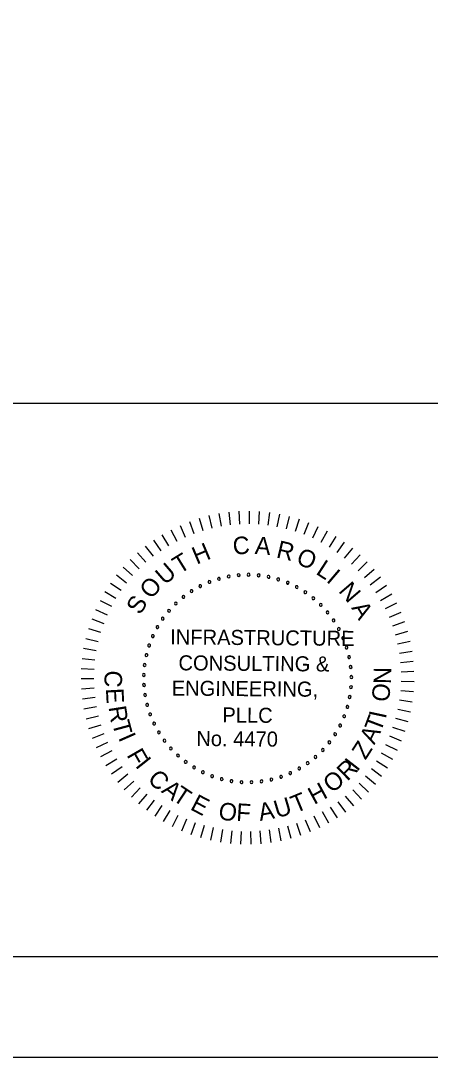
# Model space of a CAD drawing. Extents: x -125.5 to -89.4, y -5.1 to 16.9.
# Drawn here: x -100.33 to -98.29, y -5.07 to 0.08 of the extents above; entities that cross this region are included whole.
import ezdxf

# ---------------------------------------------------------------- set-up
doc = ezdxf.new("R2010")
doc.units = 0
for name, color, linetype in [('BR_BORDER LINES', 7, 'Continuous'), ('BR_TEXT', 7, 'Continuous'), ('Level 31', 7, 'Continuous')]:
    doc.layers.add(name, color=color, linetype=linetype)

msp = doc.modelspace()

# ---------------------------------------------------------------- linework, layer by layer
at = {"layer": 'BR_BORDER LINES'}
for p, q in [((-102.8989, -1.8161), (-97.5337, -1.8161)), ((-123.6994, -4.5662), (-90.0334, -4.5662))]:
    msp.add_line(p, q, dxfattribs=at)
at = {"layer": 'BR_TEXT'}
for p, q in [((-99.343, -2.3651), (-99.332, -2.4278)), ((-99.2931, -2.3579), (-99.2858, -2.4212)), ((-99.2427, -2.3538), (-99.2394, -2.4174)), ((-99.1923, -2.3527), (-99.1928, -2.4164)), ((-99.1418, -2.3548), (-99.1462, -2.4183)), ((-99.0916, -2.3599), (-99.0999, -2.423)), ((-99.0418, -2.368), (-99.0539, -2.4305)), ((-99.489, -2.4048), (-99.4667, -2.4644)), ((-99.4412, -2.3886), (-99.4226, -2.4495)), ((-99.3925, -2.3754), (-99.3776, -2.4373)), ((-98.9925, -2.3792), (-99.0084, -2.4408)), ((-98.9441, -2.3933), (-98.9637, -2.4539)), ((-98.8966, -2.4104), (-98.9199, -2.4696)), ((-99.6253, -2.4703), (-99.5926, -2.5249)), ((-99.5813, -2.4457), (-99.5519, -2.5022)), ((-99.5358, -2.4238), (-99.5099, -2.482)), ((-98.8502, -2.4303), (-98.877, -2.488)), ((-98.8051, -2.453), (-98.8354, -2.509)), ((-99.6678, -2.4975), (-99.6318, -2.55)), ((-98.7615, -2.4785), (-98.7952, -2.5325)), ((-98.7195, -2.5065), (-98.7564, -2.5584)), ((-99.7475, -2.5595), (-99.7053, -2.6072)), ((-99.7086, -2.5273), (-99.6694, -2.5775)), ((-98.6793, -2.5371), (-98.7193, -2.5866)), ((-98.6411, -2.57), (-98.684, -2.617)), ((-99.7843, -2.5941), (-99.7393, -2.6391)), ((-98.6049, -2.6052), (-98.6506, -2.6495)), ((-99.8513, -2.6695), (-99.8012, -2.7087)), ((-99.819, -2.6308), (-99.7713, -2.673)), ((-98.571, -2.6426), (-98.6193, -2.684)), ((-99.8813, -2.7102), (-99.8288, -2.7463)), ((-98.5393, -2.6819), (-98.5901, -2.7204)), ((-98.5102, -2.7232), (-98.5632, -2.7584)), ((-99.9087, -2.7526), (-99.8541, -2.7854)), ((-98.4836, -2.7661), (-98.5387, -2.798)), ((-99.9334, -2.7966), (-99.877, -2.826)), ((-98.4597, -2.8105), (-98.5166, -2.839)), ((-99.9555, -2.842), (-99.8973, -2.8679)), ((-98.4385, -2.8564), (-98.497, -2.8814)), ((-99.9747, -2.8886), (-99.9151, -2.911)), ((-98.4201, -2.9034), (-98.4801, -2.9248)), ((-100.0044, -2.9851), (-99.9426, -3)), ((-99.991, -2.9364), (-99.9302, -2.9551)), ((-98.4047, -2.9515), (-98.4659, -2.9691)), ((-100.0149, -3.0345), (-99.9522, -3.0456)), ((-98.3922, -3.0004), (-98.4544, -3.0143)), ((-100.0222, -3.0844), (-99.959, -3.0917)), ((-98.3828, -3.05), (-98.4456, -3.0601)), ((-100.0266, -3.1347), (-99.963, -3.1382)), ((-98.3763, -3.1), (-98.4397, -3.1063)), ((-100.0278, -3.1852), (-99.9641, -3.1847)), ((-98.373, -3.1504), (-98.4366, -3.1528)), ((-100.026, -3.2356), (-99.9625, -3.2313)), ((-98.3727, -3.2009), (-98.4363, -3.1994)), ((-100.0211, -3.2859), (-99.9579, -3.2777)), ((-98.3813, -3.3014), (-98.4443, -3.2922)), ((-98.3755, -3.2513), (-98.4389, -3.2459)), ((-100.0131, -3.3357), (-99.9506, -3.3237)), ((-98.3902, -3.3511), (-98.4525, -3.3381)), ((-100.0021, -3.385), (-99.9405, -3.3692)), ((-98.4021, -3.4002), (-98.4635, -3.3834)), ((-99.9882, -3.4335), (-99.9276, -3.414)), ((-98.417, -3.4484), (-98.4773, -3.4279)), ((-99.9713, -3.4811), (-99.912, -3.4579)), ((-99.9515, -3.5276), (-99.8937, -3.5008)), ((-98.4348, -3.4957), (-98.4937, -3.4715)), ((-99.9289, -3.5727), (-99.8729, -3.5425)), ((-98.4554, -3.5417), (-98.5128, -3.514)), ((-99.9037, -3.6164), (-99.8496, -3.5828)), ((-98.5049, -3.6297), (-98.5585, -3.5952)), ((-98.4789, -3.5865), (-98.5344, -3.5553)), ((-99.8758, -3.6585), (-99.8239, -3.6217)), ((-98.5336, -3.6712), (-98.5849, -3.6335)), ((-99.8454, -3.6988), (-99.7958, -3.6589)), ((-99.8126, -3.7372), (-99.7655, -3.6943)), ((-98.5983, -3.7487), (-98.6447, -3.705)), ((-98.5648, -3.7109), (-98.6137, -3.6702)), ((-99.7775, -3.7735), (-99.7331, -3.7278)), ((-98.6341, -3.7843), (-98.6777, -3.7379)), ((-99.7403, -3.8076), (-99.6988, -3.7593)), ((-99.701, -3.8393), (-99.6626, -3.7886)), ((-98.7118, -3.8487), (-98.7494, -3.7974)), ((-98.6719, -3.8177), (-98.7126, -3.7687)), ((-99.6599, -3.8687), (-99.6246, -3.8157)), ((-99.6171, -3.8954), (-99.5851, -3.8404)), ((-98.7967, -3.9032), (-98.8278, -3.8476)), ((-98.7534, -3.8772), (-98.7879, -3.8237)), ((-99.5728, -3.9195), (-99.5442, -3.8626)), ((-99.527, -3.9408), (-99.5019, -3.8823)), ((-99.48, -3.9594), (-99.4586, -3.8994)), ((-98.935, -3.9645), (-98.9555, -3.9042)), ((-98.8877, -3.9469), (-98.9118, -3.888)), ((-98.8416, -3.9264), (-98.8692, -3.8691)), ((-99.432, -3.975), (-99.4143, -3.9138)), ((-99.3832, -3.9876), (-99.3692, -3.9255)), ((-99.3336, -3.9973), (-99.3234, -3.9344)), ((-99.2836, -4.0039), (-99.2772, -3.9406)), ((-99.2332, -4.0075), (-99.2307, -3.9438)), ((-99.1827, -4.0079), (-99.1841, -3.9443)), ((-99.1323, -4.0053), (-99.1376, -3.9419)), ((-99.0821, -3.9997), (-99.0913, -3.9367)), ((-99.0324, -3.991), (-99.0454, -3.9286)), ((-98.9833, -3.9792), (-99.0001, -3.9178))]:
    msp.add_line(p, q, dxfattribs=at)
for centre, start, end in [((-99.2939, -2.6775), 10.6038, 190.6038), ((-99.2939, -2.6775), 190.6038, 10.6038), ((-99.2445, -2.6708), 5.0653, 185.0653), ((-99.2445, -2.6708), 185.0653, 5.0653), ((-99.1947, -2.6689), 359.5268, 179.5268), ((-99.1947, -2.6689), 179.5268, 359.5268), ((-99.145, -2.6718), 173.9884, 353.9884), ((-99.145, -2.6718), 353.9884, 173.9884), ((-99.0957, -2.6795), 348.4499, 168.4499), ((-99.435, -2.7255), 27.2191, 207.2191), ((-99.435, -2.7255), 207.2191, 27.2191), ((-99.3895, -2.705), 21.6807, 201.6807), ((-99.3895, -2.705), 201.6807, 21.6807), ((-99.3424, -2.6889), 16.1422, 196.1422), ((-99.3424, -2.6889), 196.1422, 16.1422), ((-99.0957, -2.6795), 168.4499, 348.4499), ((-99.0475, -2.6919), 162.9114, 342.9114), ((-99.0475, -2.6919), 342.9114, 162.9114), ((-99.0006, -2.709), 157.373, 337.373), ((-99.0006, -2.709), 337.373, 157.373), ((-98.9557, -2.7304), 151.8345, 331.8345), ((-98.9557, -2.7304), 331.8345, 151.8345), ((-99.5188, -2.7792), 38.2961, 218.2961), ((-99.5188, -2.7792), 218.2961, 38.2961), ((-99.4782, -2.7503), 32.7576, 212.7576), ((-99.4782, -2.7503), 212.7576, 32.7576), ((-98.913, -2.7561), 146.2961, 326.2961), ((-98.913, -2.7561), 326.2961, 146.2961), ((-98.873, -2.7858), 320.7576, 140.7576), ((-99.5564, -2.8119), 43.8345, 223.8345), ((-99.5564, -2.8119), 223.8345, 43.8345), ((-98.873, -2.7858), 140.7576, 320.7576), ((-98.836, -2.8192), 135.2191, 315.2191), ((-98.836, -2.8192), 315.2191, 135.2191), ((-99.6214, -2.8873), 54.9114, 234.9114), ((-99.6214, -2.8873), 234.9114, 54.9114), ((-99.5907, -2.848), 49.373, 229.373), ((-99.5907, -2.848), 229.373, 49.373), ((-98.8024, -2.8561), 129.6807, 309.6807), ((-98.8024, -2.8561), 309.6807, 129.6807), ((-99.6481, -2.9293), 60.4499, 240.4499), ((-99.6481, -2.9293), 240.4499, 60.4499), ((-98.7726, -2.896), 124.1422, 304.1422), ((-98.7726, -2.896), 304.1422, 124.1422), ((-98.7467, -2.9386), 118.6038, 298.6038), ((-98.7467, -2.9386), 298.6038, 118.6038), ((-99.6706, -2.9738), 65.9884, 245.9884), ((-99.6706, -2.9738), 245.9884, 65.9884), ((-98.7251, -2.9835), 113.0653, 293.0653), ((-98.7251, -2.9835), 293.0653, 113.0653), ((-99.6888, -3.0202), 71.5268, 251.5268), ((-99.6888, -3.0202), 251.5268, 71.5268), ((-98.7079, -3.0302), 107.5268, 287.5268), ((-98.7079, -3.0302), 287.5268, 107.5268), ((-99.7024, -3.0681), 77.0653, 257.0653), ((-99.7024, -3.0681), 257.0653, 77.0653), ((-98.6953, -3.0785), 101.9884, 281.9884), ((-98.6953, -3.0785), 281.9884, 101.9884), ((-99.7113, -3.1172), 82.6038, 262.6038), ((-99.7113, -3.1172), 262.6038, 82.6038), ((-98.6874, -3.1277), 96.4499, 276.4499), ((-98.6874, -3.1277), 276.4499, 96.4499), ((-99.7154, -3.1668), 88.1422, 268.1422), ((-99.7154, -3.1668), 268.1422, 88.1422), ((-98.6843, -3.1774), 90.9114, 270.9114), ((-98.6843, -3.1774), 270.9114, 90.9114), ((-99.7147, -3.2167), 93.6807, 273.6807), ((-99.7147, -3.2167), 273.6807, 93.6807), ((-98.686, -3.2272), 85.373, 265.373), ((-98.686, -3.2272), 265.373, 85.373), ((-99.7092, -3.2662), 99.2191, 279.2191), ((-99.7092, -3.2662), 279.2191, 99.2191), ((-98.6926, -3.2766), 79.8345, 259.8345), ((-98.6926, -3.2766), 259.8345, 79.8345), ((-99.6989, -3.3149), 104.7576, 284.7576), ((-99.6989, -3.3149), 284.7576, 104.7576), ((-98.7038, -3.3251), 74.2961, 254.2961), ((-98.7038, -3.3251), 254.2961, 74.2961), ((-99.684, -3.3625), 110.2961, 290.2961), ((-99.684, -3.3625), 290.2961, 110.2961), ((-98.7197, -3.3724), 68.7576, 248.7576), ((-98.7197, -3.3724), 248.7576, 68.7576), ((-99.6646, -3.4084), 115.8345, 295.8345), ((-99.6646, -3.4084), 295.8345, 115.8345), ((-99.6408, -3.4522), 121.373, 301.373), ((-99.6408, -3.4522), 301.373, 121.373), ((-98.7401, -3.4179), 63.2191, 243.2191), ((-98.7401, -3.4179), 243.2191, 63.2191), ((-99.6129, -3.4935), 126.9114, 306.9114), ((-99.6129, -3.4935), 306.9114, 126.9114), ((-98.7934, -3.5019), 52.1422, 232.1422), ((-98.7934, -3.5019), 232.1422, 52.1422), ((-98.7647, -3.4612), 57.6807, 237.6807), ((-98.7647, -3.4612), 237.6807, 57.6807), ((-99.5812, -3.5319), 132.4499, 312.4499), ((-99.5812, -3.5319), 312.4499, 132.4499), ((-98.826, -3.5396), 46.6038, 226.6038), ((-98.826, -3.5396), 226.6038, 46.6038), ((-99.5459, -3.5671), 137.9884, 317.9884), ((-99.5459, -3.5671), 317.9884, 137.9884), ((-99.5074, -3.5987), 143.5268, 323.5268), ((-99.5074, -3.5987), 323.5268, 143.5268), ((-98.9012, -3.6049), 35.5268, 215.5268), ((-98.9012, -3.6049), 215.5268, 35.5268), ((-98.862, -3.5741), 41.0653, 221.0653), ((-98.862, -3.5741), 221.0653, 41.0653), ((-99.466, -3.6264), 149.0653, 329.0653), ((-99.466, -3.6264), 329.0653, 149.0653), ((-99.4221, -3.65), 154.6038, 334.6038), ((-99.4221, -3.65), 334.6038, 154.6038), ((-98.9875, -3.6545), 24.4499, 204.4499), ((-98.9875, -3.6545), 204.4499, 24.4499), ((-98.9431, -3.6317), 29.9884, 209.9884), ((-98.9431, -3.6317), 209.9884, 29.9884), ((-99.3761, -3.6693), 160.1422, 340.1422), ((-99.3761, -3.6693), 340.1422, 160.1422), ((-99.3285, -3.684), 165.6807, 345.6807), ((-99.3285, -3.684), 345.6807, 165.6807), ((-99.2797, -3.6941), 171.2191, 351.2191), ((-99.2797, -3.6941), 351.2191, 171.2191), ((-99.2302, -3.6994), 356.7576, 176.7576), ((-99.2302, -3.6994), 176.7576, 356.7576), ((-99.1803, -3.6999), 2.2961, 182.2961), ((-99.1803, -3.6999), 182.2961, 2.2961), ((-99.1307, -3.6956), 7.8345, 187.8345), ((-99.1307, -3.6956), 187.8345, 7.8345), ((-99.0817, -3.6865), 13.373, 193.373), ((-99.0817, -3.6865), 193.373, 13.373), ((-99.0338, -3.6728), 18.9114, 198.9114), ((-99.0338, -3.6728), 198.9114, 18.9114)]:
    msp.add_arc(centre, 0.00701, start, end, dxfattribs=at)
at = {"layer": 'Level 31'}
msp.add_lwpolyline([(-125.5328, -5.0661), (-89.5328, -5.0661), (-89.5328, 16.9339), (-125.5328, 16.9339)], close=True, dxfattribs=at)

# ---------------------------------------------------------------- texts
at = {"layer": 'BR_TEXT'}
for s, height, rotation, p in [('H', 0.0872, 22.7882, (-99.453, -2.6197)), ('C', 0.0872, 4.7281, (-99.2702, -2.5703)), ('A', 0.0872, 355.6981, (-99.1657, -2.5654)), ('R', 0.0872, 346.6681, (-99.0615, -2.5824)), ('T', 0.0872, 31.8182, (-99.5379, -2.6674)), ('O', 0.0872, 337.638, (-98.9637, -2.6122)), ('U', 0.0872, 40.8482, (-99.6112, -2.7235)), ('L', 0.0872, 327.108, (-98.8649, -2.6626)), ('I', 0.0872, 319.578, (-98.8123, -2.7005)), ('O', 0.0872, 49.8782, (-99.6782, -2.7945)), ('N', 0.0872, 310.548, (-98.7515, -2.7512)), ('S', 0.0872, 58.9083, (-99.7336, -2.8727)), ('A', 0.0872, 301.5179, (-98.6864, -2.8336)), ('INFRASTRUCTURE', 0.074771, 359.5268, (-99.585, -3.0152)), ('CONSULTING &', 0.074771, 359.5268, (-99.5437, -3.1438)), ('N', 0.0872, 89.2085, (-98.4872, -3.2124)), ('C', 0.0872, 267.025, (-99.9086, -3.1426)), ('E', 0.0872, 273.025, (-99.9042, -3.2342)), ('ENGINEERING,', 0.074771, 359.5268, (-99.5773, -3.2693)), ('O', 0.0872, 83.2085, (-98.4982, -3.3038)), ('R', 0.0872, 279.025, (-99.8914, -3.3265)), ('PLLC', 0.07477, 359.5268, (-99.3256, -3.4028)), ('T', 0.0872, 285.025, (-99.874, -3.4053)), ('T', 0.0872, 69.3954, (-98.5394, -3.4556)), ('I', 0.0872, 77.9093, (-98.5137, -3.3881)), ('No. 4470', 0.07477, 359.5268, (-99.4551, -3.5197)), ('A', 0.0872, 63.3954, (-98.5702, -3.516)), ('I', 0.0872, 293.7713, (-99.8443, -3.4784)), ('Z', 0.0872, 57.3954, (-98.6141, -3.5923)), ('F', 0.0872, 299.7713, (-99.8031, -3.5644)), ('I', 0.0872, 308.5268, (-99.761, -3.6183)), ('R', 0.0872, 44.5268, (-98.7045, -3.6973)), ('I', 0.0872, 52.3339, (-98.6551, -3.65)), ('C', 0.0872, 314.5268, (-99.7017, -3.6884)), ('O', 0.0872, 38.5268, (-98.7811, -3.7572)), ('A', 0.0872, 320.5268, (-99.6325, -3.747)), ('H', 0.0872, 28.5268, (-98.8692, -3.8132)), ('T', 0.0872, 326.5268, (-99.5781, -3.7855)), ('T', 0.0872, 22.5268, (-98.9624, -3.855)), ('E', 0.0872, 332.5268, (-99.4895, -3.8332)), ('O', 0.0872, 350.5268, (-99.3494, -3.8821)), ('F', 0.0872, 356.5268, (-99.2579, -3.8912)), ('A', 0.0872, 10.5268, (-99.138, -3.8929)), ('U', 0.0872, 16.5268, (-99.0541, -3.8794))]:
    msp.add_text(s, height=height, rotation=rotation, dxfattribs=at).set_placement(p)

doc.saveas('drawing.dxf')
